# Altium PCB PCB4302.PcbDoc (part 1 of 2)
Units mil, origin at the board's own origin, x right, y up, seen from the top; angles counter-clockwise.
Board outline 1574.8 x 1476.38 mil, 4 copper layers (Top, Inner Layer 2, Inner Layer 3, Bottom), stack 35.4 mil thick; 37 components, 68 nets, 208 pads, 290 vias.
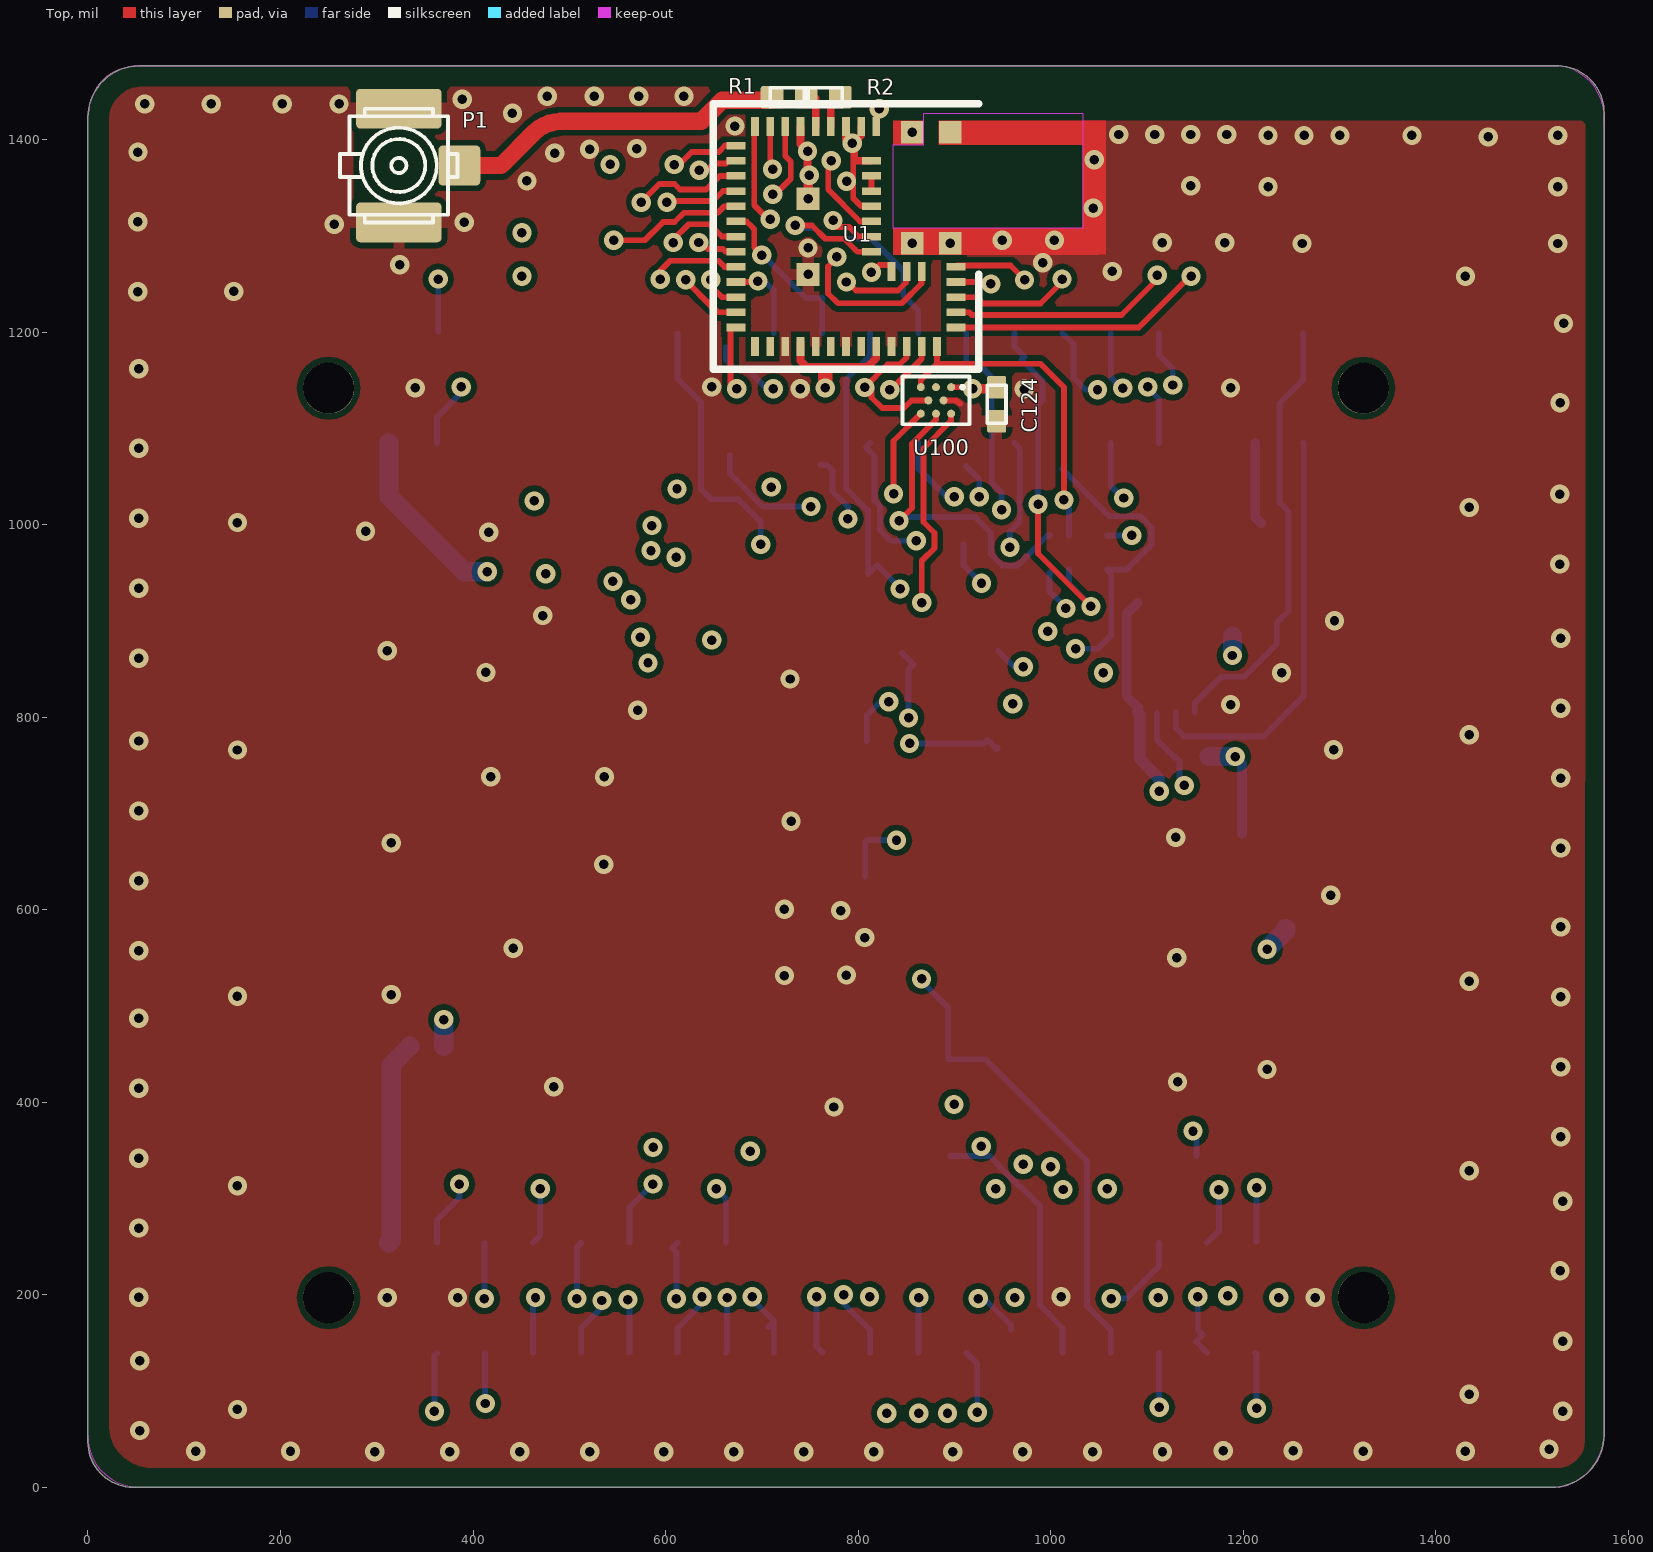
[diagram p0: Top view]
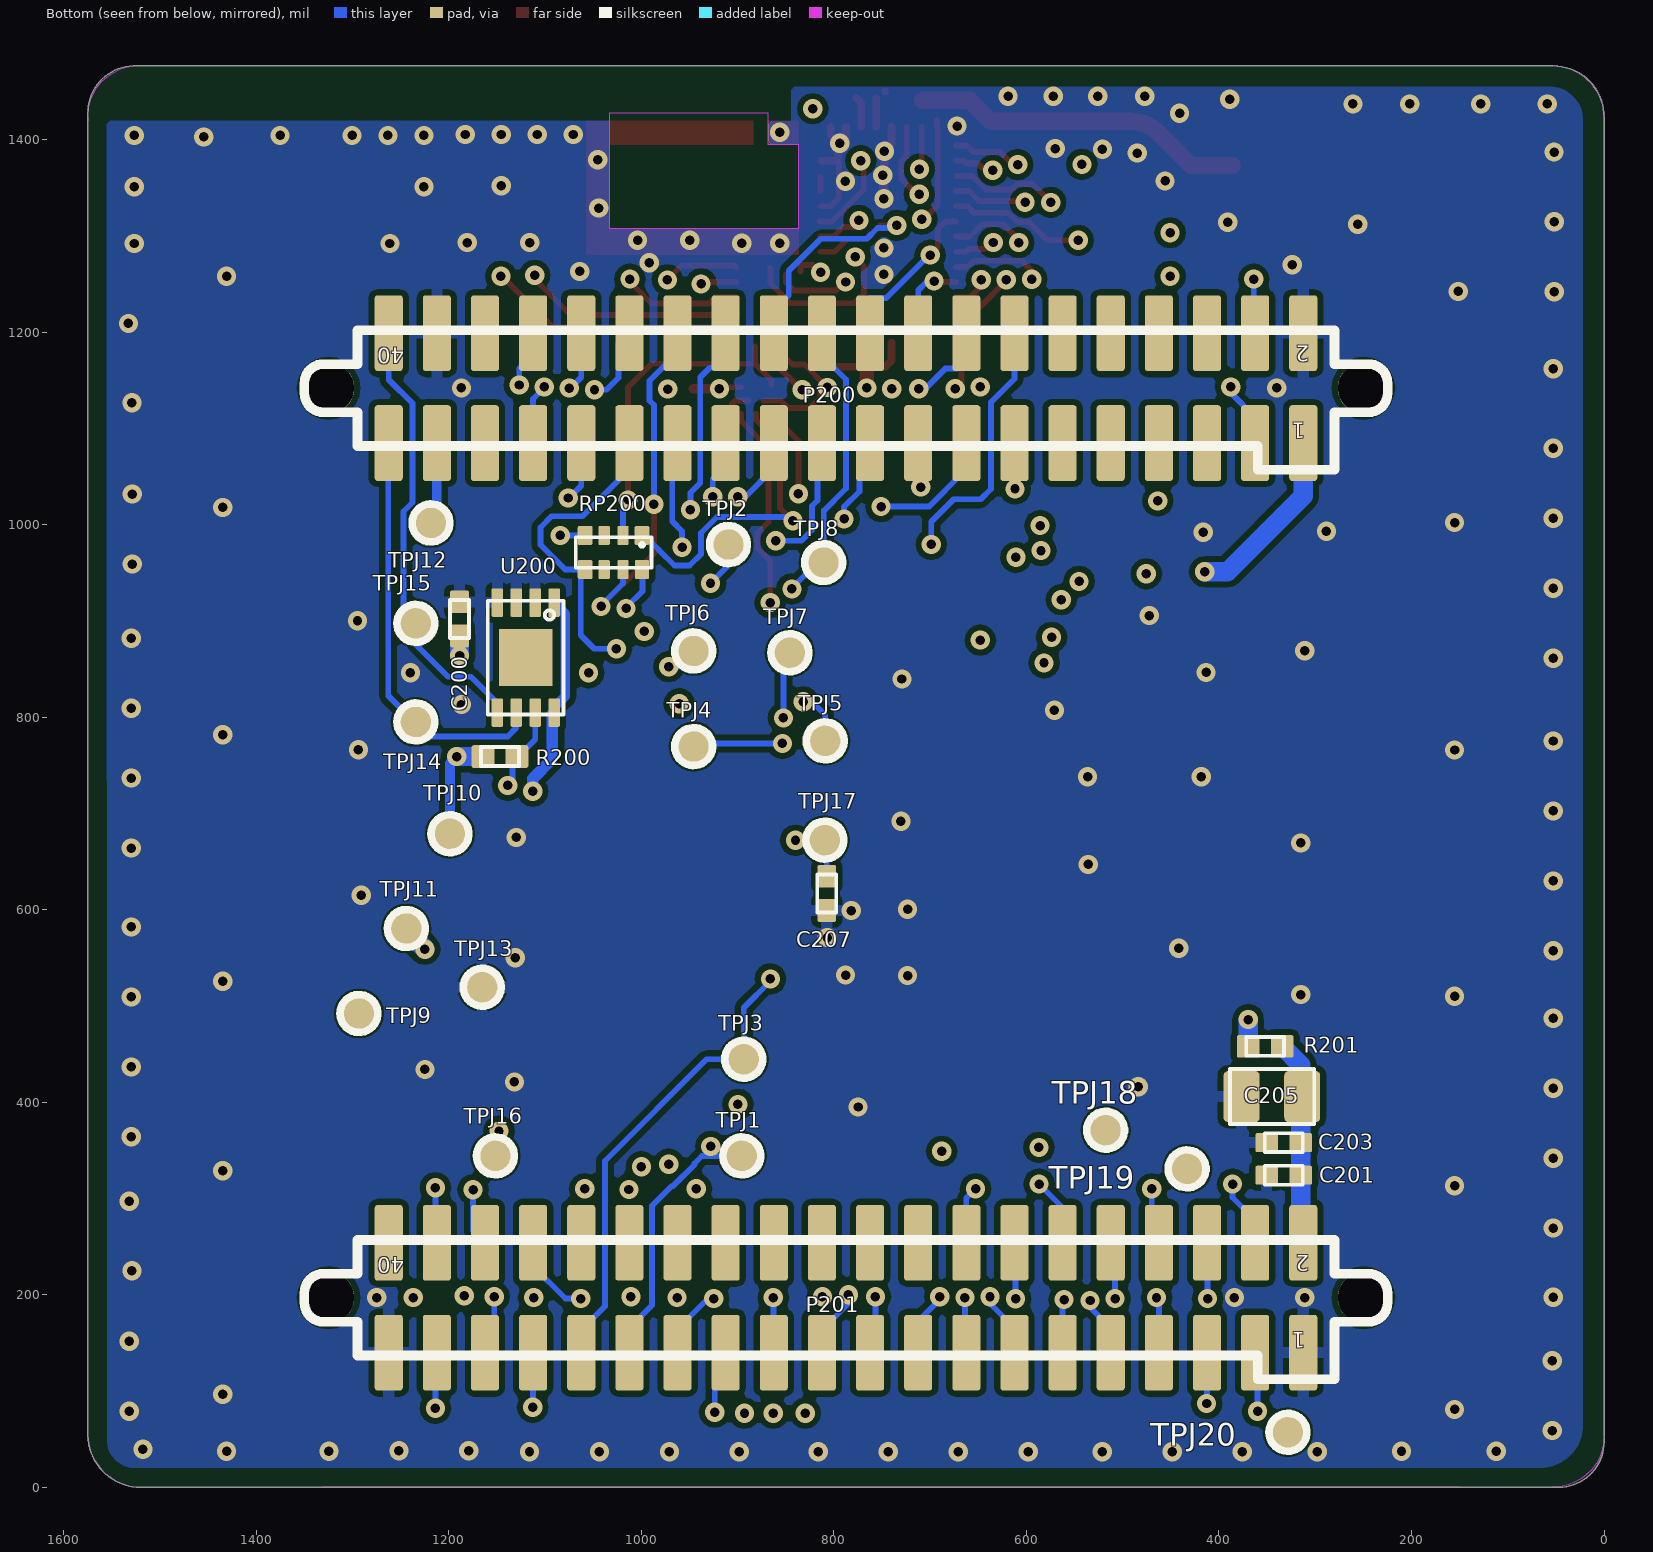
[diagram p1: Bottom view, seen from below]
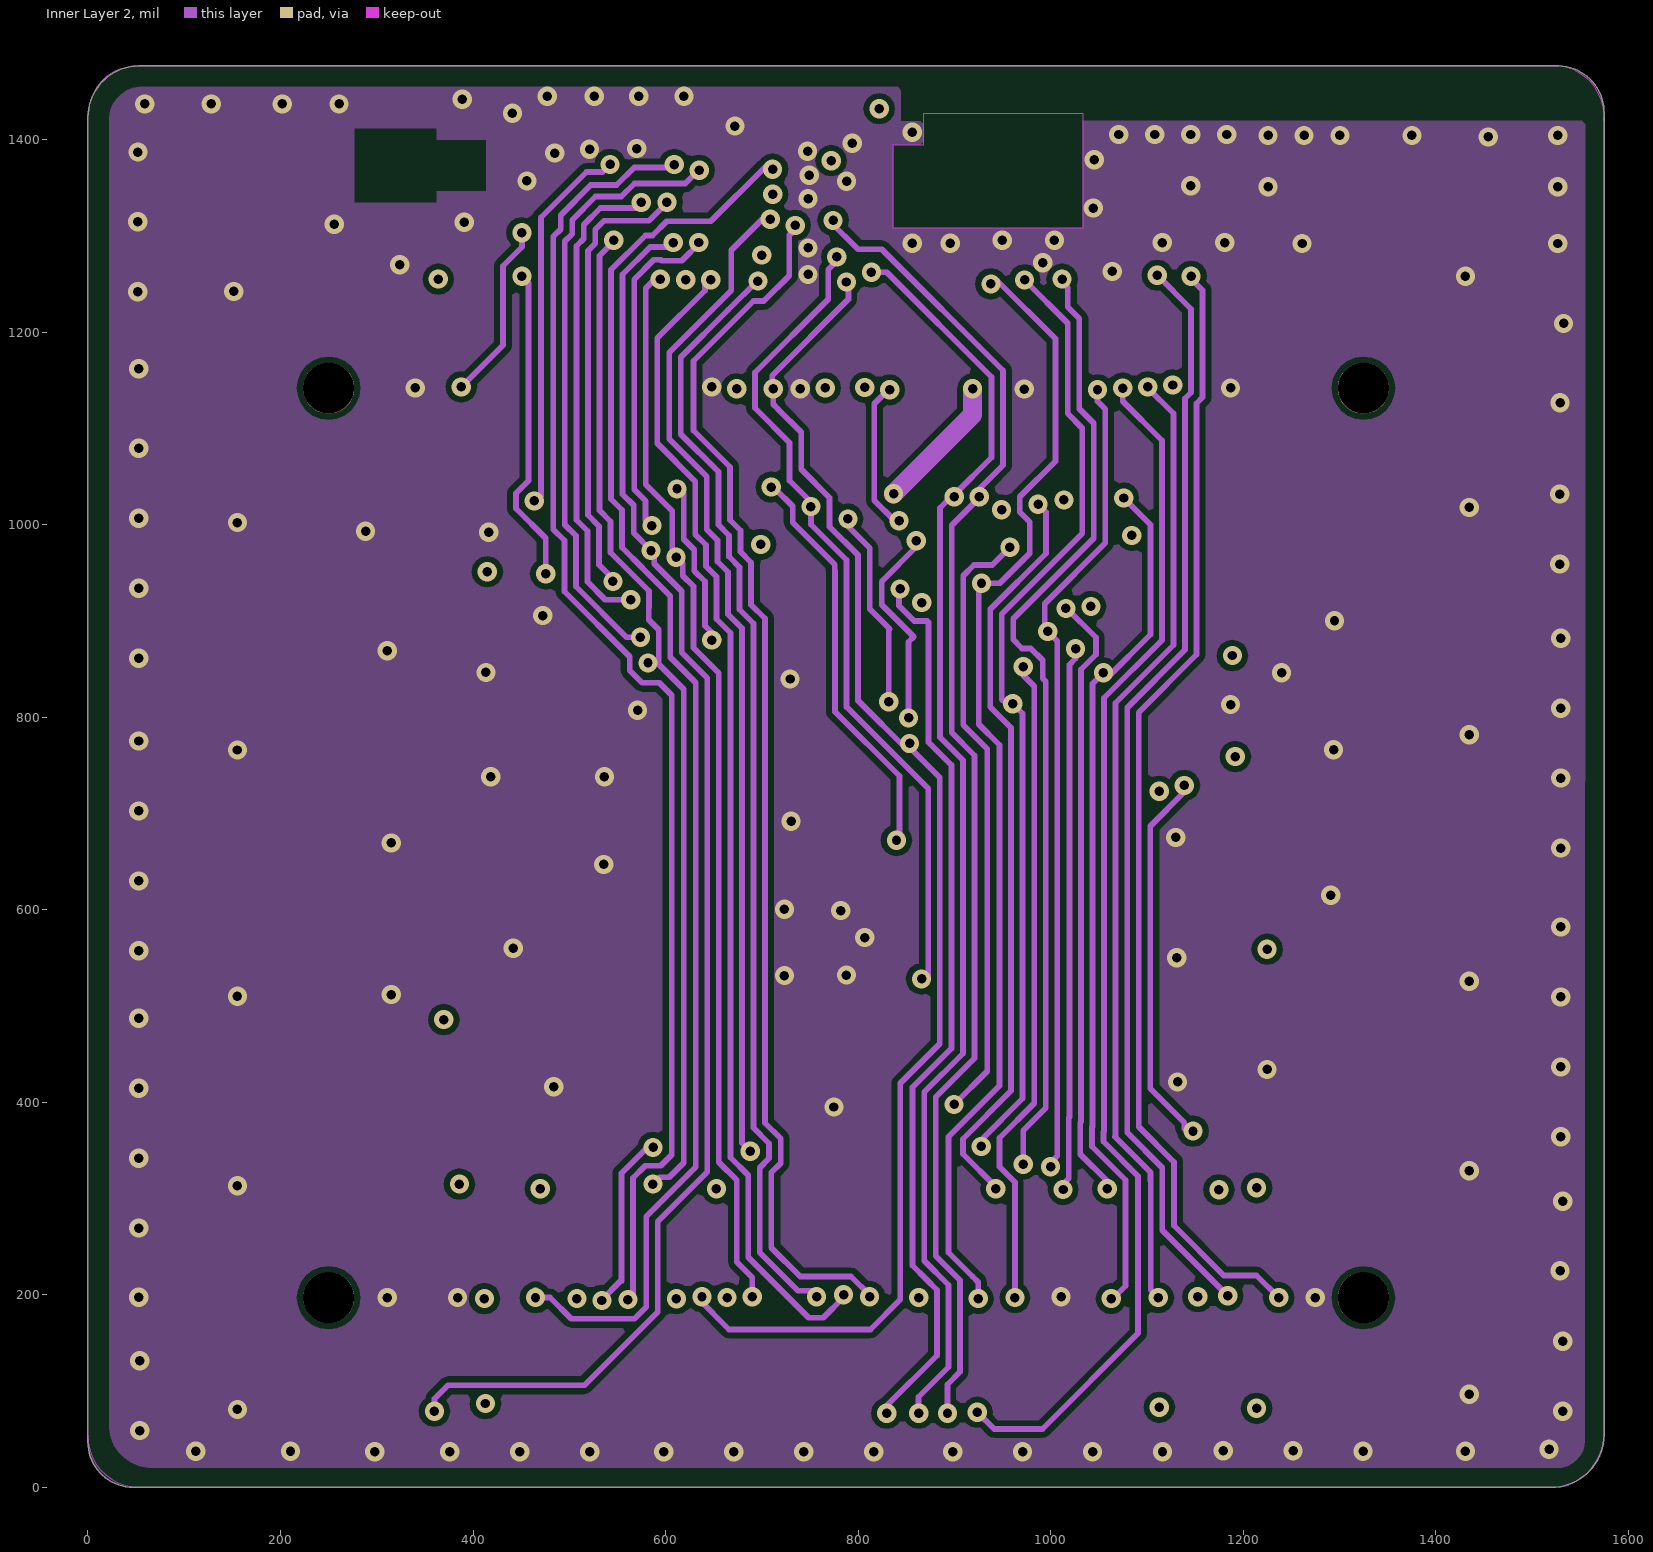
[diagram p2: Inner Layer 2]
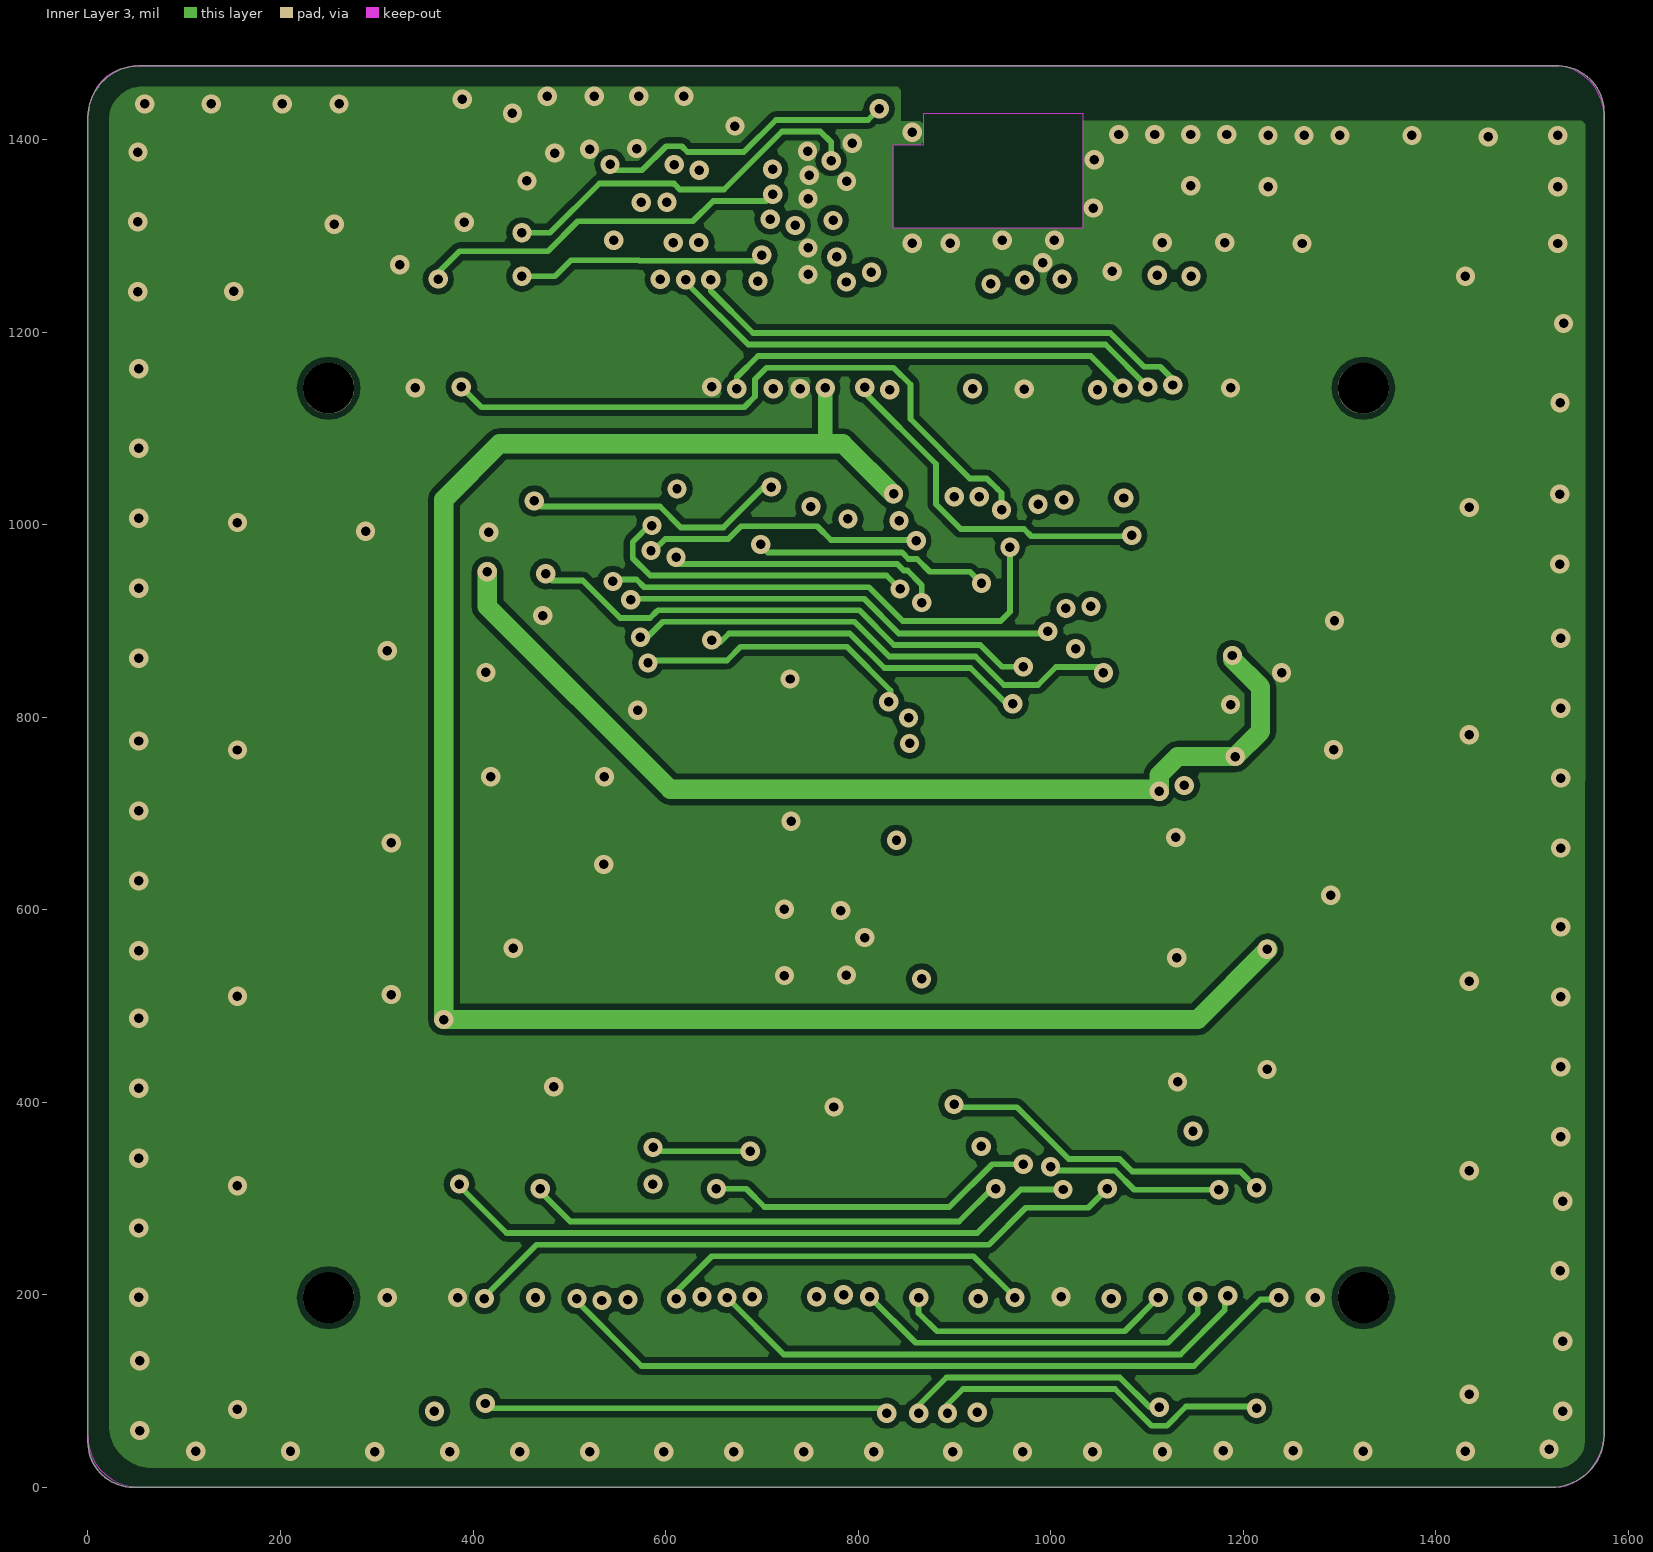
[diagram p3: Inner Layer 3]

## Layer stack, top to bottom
Solder Mask Top: solder mask 0.4, Solder Resist, Dk 3.5
Top: signal copper 1.35
Dielectric 1: dielectric 10, FR-4, Dk 4.3
Inner Layer 2: signal copper 1.35
Dielectric2: dielectric 10, FR-4, Dk 4.3
Inner Layer 3: signal copper 1.35
Dielectric3: dielectric 10, FR-4, Dk 4.3
Bottom: signal copper 1.35
Solder Mask Bottom: solder mask 0.4, Solder Resist, Dk 3.5

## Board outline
46.75,0 cw(c46.96,46.96) 0,47.18 0,1423.11 cw(c53,1423.38) 52.74,1476.38 1527.85,1476.38 cw(c1526.72,1428.3) 1574.8,1427.17 1574.8,54.22 cw(c1520.4,54.4) 1520.21,0

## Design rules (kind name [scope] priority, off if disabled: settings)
Clearance [All] p1: gap=6
Clearance 50Ohm [InNet('NetP1_1')] p2: gap=10
ComponentClearance "ComponentClearance -jumper overlap" [InComponent('R1') OR InComponent('R2') OR InComponent('U1') vs InComponent('R1') OR InComponent('R2') OR InComponent('U1')] p1: gap=0 collisioncheckmode=3 verticalgap=0 showdistances=FALSE
ComponentClearance "ComponentClearance - Default - DEFAULT" [All] p2: gap=6 collisioncheckmode=3 verticalgap=10 showdistances=FALSE
FanoutControl Fanout_Small [(CompPinCount < 5)] p3: bgadir=Out bgaviamode=Centered fanoutstyle=Auto fanoutdirection=OutThenIn viagrid=1 // Fanout_Small (Default Rule)
FanoutControl Fanout_SOIC [IsSOIC] p4: bgadir=Out bgaviamode=Centered fanoutstyle=Auto fanoutdirection=Alternating viagrid=1 // Fanout_SOIC (Default Rule)
HoleToHoleClearance HoleToHoleClearance-U1toPAD [Incomponent('U1') vs IsVia] p1: gap=0 allowstackedmicrovias=TRUE
HoleToHoleClearance HoleToHoleClearance-AT1toPAD [Incomponent('AT1') vs IsPAD] p2: gap=0 allowstackedmicrovias=TRUE
HoleToHoleClearance HoleToHoleClearance-U201toPAD [Incomponent('U201') vs IsVia] p3: gap=0 allowstackedmicrovias=TRUE
HoleToHoleClearance "HoleToHoleClearance - Default - DEFAULT" [All] p4: gap=6 allowstackedmicrovias=TRUE
MaxMinImpedance "Default Impedance" [All] p1: minimum=50.00 maximum=150.0
MinimumSolderMaskSliver [All] p1: minsoldermaskwidth=4
PlaneClearance [All] p1: clearance=6
PlaneConnect "Default PlaneConnect" [All] p1: planeconnectstyle=Relief reliefexpansion=20 reliefentries=4 reliefconductorwidth=16 reliefairgap=6
PolygonConnect "PolygonConnect _ GND Via" [IsVIa] p1: connectstyle=Direct reliefconductorwidth=10 reliefentries=4 polygonreliefangle="90 Angle" airgapwidth=10
PolygonConnect "PolygonConnect - Default SMT" [IsSMTPin] p2: connectstyle=Relief reliefconductorwidth=12 reliefentries=4 polygonreliefangle="90 Angle" airgapwidth=6
PolygonConnect "PolygonConnect - Default Pad" [All] p3: connectstyle=Relief reliefconductorwidth=16 reliefentries=4 polygonreliefangle="45 Angle" airgapwidth=6
RoutingLayers "RoutingLayers - Default - DEFAULT" [All] p1: top layer_v5=TRUE mid layer 1_v5=TRUE mid layer 2_v5=TRUE bottom layer_v5=TRUE
RoutingPriority "RoutingPriority - Default - DEFAULT" [All] p1: routingpriority=3
RoutingTopology "Default Routing Topology" [All] p1: topology=Shortest
RoutingVias "RoutingVias - Default - DEFAULT" [All] p1: holewidth=6 width=15 viastyle="Through Hole" minholewidth=6 minwidth=15 maxholewidth=10 maxwidth=20
SilkToSilkClearance [All] p1: silktosilkclearance=4
SilkToSolderMaskClearance [IsPad] p1: minsilkscreentomaskgap=4 clearancetoexposedcopper=TRUE
SolderMaskExpansion SolderMaskExpansion_via [IsVia] p1: expansion=-100
SolderMaskExpansion [All] p2: expansion=2
Width "Default Width" [All] p1: maxlimit=50 minlimit=6 preferedwidth=6 minimp=50.000000 maximp=50.000000 favimp=50.000000
18 further rules are at their usual default settings.

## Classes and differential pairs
component class "01_ Title Page": PCB1
component class "02_ RF, Antenna and Pow": P1 R1 R2 SH101
component class "03_ EFR32 I_O Port Conn": C124 C207 RP200 U1 U100
component class "04_ WSTK Connectors & B": C200 C201 C203 C205 P200 P201 R200 R201 TPJ1 TPJ2 TPJ3 TPJ4 TPJ5 TPJ6 TPJ7 TPJ8 TPJ9 TPJ10 TPJ11 TPJ12 TPJ13 TPJ14 TPJ15 TPJ16 TPJ17 TPJ18 TPJ19 TPJ20 U200
net class RADIO_PA[5..0]: RADIO_PA0 RADIO_PA1 RADIO_PA2 RADIO_PA3 RADIO_PA4 RADIO_PA5
net class RADIO_PB[15..11]: RADIO_PB11 RADIO_PB12 RADIO_PB13 RADIO_PB14 RADIO_PB15
net class RADIO_PC[11..6]: RADIO_PC6 RADIO_PC7 RADIO_PC8 RADIO_PC9 RADIO_PC10 RADIO_PC11
net class RADIO_PD[15..9]: RADIO_PD9 RADIO_PD10 RADIO_PD11 RADIO_PD12 RADIO_PD13 RADIO_PD14 RADIO_PD15
net class RADIO_PF[7..0]: RADIO_PF0 RADIO_PF1 RADIO_PF2 RADIO_PF3 RADIO_PF4 RADIO_PF5 RADIO_PF6 RADIO_PF7
net class WSTK_F[21..0]: WSTK_F4 WSTK_F15 WSTK_F16
net class WSTK_P[45..0]: WSTK_P3 WSTK_P15 WSTK_P17 WSTK_P19 WSTK_P21 WSTK_P23 WSTK_P25 WSTK_P27 WSTK_P29 WSTK_P38 WSTK_P39 WSTK_P40 WSTK_P41 WSTK_P42 WSTK_P43 WSTK_P44 WSTK_P45

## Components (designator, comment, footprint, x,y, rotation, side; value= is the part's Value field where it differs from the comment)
C124 "0.1uF" C0402_L 943.9,1125 r270 top
C200 "100N" C0402_L 1188.85,902 r90 bottom
C201 "100N" C0402_L 332.67,324.14 r0 bottom
C203 "100N" C0402_L 332.67,357.99 r0 bottom
C205 "10U" C0805_L 344.97,405.82 r0 bottom
C207 "100N" C0402_L 807.4,616.85 r270 bottom
P1 "U.FL" "COAX_HIROSE_U.FL_CL331-0471 - duplicate" 322.85,1373 r270 top
P200 "SOCKET_2X20_1.27MM_SMD" SAM_SFC-120-T2-D-A-2X20_SNUM 787.4,1141.73 r0 bottom locked
P201 "SOCKET_2X20_1.27MM_SMD" SAM_SFC-120-T2-D-A-2X20_SNUM 787.4,196.85 r0 bottom locked
R1 "0R" R0402_L 728.35,1443.9 r180 top
R2 "0R" R0402_L 763.78,1443.9 r180 top
R200 "10K" R0402_L 1146.85,759 r0 bottom
R201 "0R" R0402_L 351.96,457.99 r0 bottom
RP200 "100R" RES_MNR04-8 1028.85,971 r0 bottom
TPJ1 "PCB_PAD" TP_1.0_SMD 895.67,344.21 r180 bottom locked
TPJ2 "PCB_PAD" TP_1.0_SMD 909.45,979.25 r180 bottom locked
TPJ3 "PCB_PAD" TP_1.0_SMD 893.7,444.61 r180 bottom locked
TPJ4 "PCB_PAD" TP_1.0_SMD 945.67,769.41 r180 bottom locked
TPJ5 "PCB_PAD" TP_1.0_SMD 809.05,775.32 r180 bottom locked
TPJ6 "PCB_PAD" TP_1.0_SMD 945.67,868.72 r180 bottom locked
TPJ7 "PCB_PAD" TP_1.0_SMD 845.67,866.93 r180 bottom locked
TPJ8 "PCB_PAD" TP_1.0_SMD 810.63,960.63 r180 bottom locked
TPJ9 "PCB_PAD" TP_1.0_SMD 1293.31,492.13 r180 bottom locked
TPJ10 "PCB_PAD" TP_1.0_SMD 1198.82,678.86 r180 bottom locked
TPJ11 "PCB_PAD" TP_1.0_SMD 1244.09,580.43 r180 bottom locked
TPJ12 "PCB_PAD" TP_1.0_SMD 1218.5,1001.69 r180 bottom locked
TPJ13 "PCB_PAD" TP_1.0_SMD 1165.35,519.41 r180 bottom locked
TPJ14 "PCB_PAD" TP_1.0_SMD 1234.25,795 r180 bottom locked
TPJ15 "PCB_PAD" TP_1.0_SMD 1234.25,897.36 r180 bottom locked
TPJ16 "PCB_PAD" TP_1.0_SMD 1151.57,344.21 r180 bottom locked
TPJ17 "PCB_PAD" TP_1.0_SMD 809.35,672.23 r180 bottom locked
TPJ18 "PCB_PAD" TP_1.0_SMD 517.72,370.87 r90 bottom
TPJ19 "PCB_PAD" TP_1.0_SMD 433.07,330.71 r90 bottom
TPJ20 "PCB_PAD" TP_1.0_SMD 328.35,57.09 r90 bottom
U1 "BGM121" EFR_SIP 787.4,1299.21 r270 top
U100 "MX25R8035F" BGA8_M040_1.24x1.75_WLCSP 880.85,1129 r270 top
U200 "24AA024" TDFN8_M050_2.0x3.0_EP 1120.08,861.81 r0 bottom

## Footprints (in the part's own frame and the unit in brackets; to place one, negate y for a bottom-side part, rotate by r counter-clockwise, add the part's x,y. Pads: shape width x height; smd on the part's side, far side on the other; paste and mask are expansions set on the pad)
BGA8_M040_1.24x1.75_WLCSP [mm] "BGA, 8 pin. U100"
  round 0.21 smd mask+0.051: A1(-0.35,0.4) A3(0.35,0.4) B2(0,0.2) C1(-0.35,0) C3(0.35,0) D2(0,-0.2) E1(-0.35,-0.4) E3(0.35,-0.4)
  silkscreen extent -0.63,-0.89 0.63,0.88, body extent -0.63,-0.89 0.63,0.88, height 0.52
C0402_L [mm] "Chip Capacitor, 2-Leads, Body 1.0x0.5mm, IPC High Density"
  rrect20% 0.6x0.5 smd mask+0.051: 1(-0.45,0) 2(0.45,0)
  silkscreen extent -0.5,-0.25 0.5,0.25, body extent -0.5,-0.25 0.5,0.25, height 0.6
C0805_L [mm]
  rrect25% 0.95x1.35 smd: 1(-0.8,0) 2(0.8,0)
  silkscreen extent -1.12,-0.72 1.1,0.72, body extent -1.1,-0.72 1.1,0.72, height 1.45
"COAX_HIROSE_U.FL_CL331-0471 - duplicate" [mm]
  rrect20% 1.05x1.1 smd mask+0.051: 1(0,1.6)
  rrect20% 1.05x2.25 smd mask+0.051: 2(-1.5,0) 3(1.5,0)
  Top pour cut-out: -0.85,0.9 0.85,0.9 0.85,0.9 0.85,-1.2 -0.85,-1.2 -0.85,-1.2
  silkscreen extent -1.5,-1.55 1.5,1.55, body extent -1.3,-1.55 1.3,1.3, height 0.9
EFR_SIP [mm]
  rect 0.5x0.2 smd mask+0.015: 1(-2.9,0.8) 2(-2.9,0.4) 3(-2.9,0) 4(-2.9,-0.4) 5(-2.9,-0.8) 6(-2.9,-1.2) 7(-2.9,-1.6) 8(-2.9,-2) 9(-2.9,-2.4) 23(2.9,-2.4) 24(2.9,-2) 25(2.9,-1.6) 26(2.9,-1.2) 27(2.9,-0.8) 28(2.9,-0.4) 29(2.9,0) 30(2.9,0.4) 31(2.9,0.8) 32(2.9,1.2) 33(2.9,1.6) 34(2.9,2) 35(2.9,2.4) 41(0.925,2) 42(0.925,1.6) 43(0.925,1.2)
  rect 0.2x0.5 smd mask+0.015: 10(-2.4,-2.9) 11(-2,-2.9) 12(-1.6,-2.9) 13(-1.2,-2.9) 14(-0.8,-2.9) 15(-0.4,-2.9) 16(0,-2.9) 17(0.4,-2.9) 18(0.8,-2.9) 19(1.2,-2.9) 20(1.6,-2.9) 21(2,-2.9) 22(2.4,-2.9) 36(2.4,2.9) 37(2,2.9) 38(1.6,2.9) 39(1.2,2.9) 40(0.8,2.9) 44(0.4,0.675) 45(0,0.675) 46(-0.4,0.675) 47(-0.8,0.675) 48(-1.2,0.675) 49(-1.6,0.675) 50(-2,0.675)
  rect 0.6x0.6 smd mask+0.015: 51(-1,-1) 52(1,-1) 53(-2.75,2.75) 54(-2.75,1.75) 55(0.175,1.75) 56(0.175,2.75)
  Top region: -3.05,2.05 -3.05,1.25 -2.425,1.25 -2.425,2.05
  Top region: -0.225,3.05 -0.225,1.25 0.475,1.25 0.475,3.05
  Top pour cut-out: -0.225,1.25 -2.425,1.25 -2.425,2.05 -3.25,2.05 -3.25,2.45 -2.425,2.45 -2.425,6.25 -0.225,6.25
  Top region: -3.05,2.45 -2.425,2.45 -2.425,6.65 -3.05,6.65
  Top region: -3.05,6.25 0.463,6.25 0.463,6.85 -3.05,6.85
  Top region: -0.225,2.45 0.475,2.45 0.475,6.65 -0.225,6.65
  Keep-Out Layer pour cut-out: -3.25,6.25 -0.225,6.25 -0.225,1.25 -2.425,1.25 -2.425,2.05 -3.25,2.05 -3.25,2.45
  silkscreen extent -3.5,-3.5 3.5,3.5
R0402_L [mm] "Chip Resistor, 2-Leads, Body 1.0x0.5mm, IPC High Density"
  rrect20% 0.6x0.6 smd mask+0.051: 1(-0.45,0) 2(0.45,0)
  silkscreen extent -0.5,-0.25 0.5,0.25, body extent -0.5,-0.25 0.5,0.25, height 0.6
RES_MNR04-8 [mm] "Chip resistor network 8pin"
  rrect20% 0.39x0.5 smd mask+0.051: 1(-0.75,-0.45) 4(0.75,-0.45) 5(0.75,0.45)
  rrect20% 0.3x0.5 smd mask+0.051: 2(-0.25,-0.45) 3(0.25,-0.45) 6(0.25,0.45) 7(-0.25,0.45)
  rrect20% 0.38x0.5 smd mask+0.051: 8(-0.75,0.45)
  silkscreen extent -1,-0.4 1,0.4, body extent -1,-0.4 1,0.4, height 0.5
SAM_SFC-120-T2-D-A-2X20_SNUM [mm]
  rrect20% 0.74x2 smd mask+0.05: 1(-12.065,1.45) 2(-12.065,-1.45) 3(-10.795,1.45) 4(-10.795,-1.45) 5(-9.525,1.45) 6(-9.525,-1.45) 7(-8.255,1.45) 8(-8.255,-1.45) 9(-6.985,1.45) 10(-6.985,-1.45) 11(-5.715,1.45) 12(-5.715,-1.45) 13(-4.445,1.45) 14(-4.445,-1.45) 15(-3.175,1.45) 16(-3.175,-1.45) 17(-1.905,1.45) 18(-1.905,-1.45) 19(-0.635,1.45) 20(-0.635,-1.45) 21(0.635,1.45) 22(0.635,-1.45) 23(1.905,1.45) 24(1.905,-1.45) 25(3.175,1.45) 26(3.175,-1.45) 27(4.445,1.45) 28(4.445,-1.45) 29(5.715,1.45) 30(5.715,-1.45) 31(6.985,1.45) 32(6.985,-1.45) 33(8.255,1.45) 34(8.255,-1.45) 35(9.525,1.45) 36(9.525,-1.45) 37(10.795,1.45) 38(10.795,-1.45) 39(12.065,1.45) 40(12.065,-1.45)
  round 1.35 hole 1.35 unplated paste-5.563 mask-5.563: M1(13.652,0) M2(-13.652,0)
  silkscreen extent -14.29,-1.53 14.29,2.15, body extent -14.65,-1.58 14.65,2.25, height 4.57
TDFN8_M050_2.0x3.0_EP [mm] "TDFN8_M050_2.0x3.0_EP"
  rrect20% 0.3x0.75 smd mask+0.051: 1(-0.75,-1.45) 2(-0.25,-1.45) 3(0.25,-1.45) 4(0.75,-1.45) 5(0.75,1.45) 6(0.25,1.45) 7(-0.25,1.45) 8(-0.75,1.45)
  rect 1.4x1.5 smd mask+0.051: 9(0,0)
  silkscreen extent -1,-1.5 1,1.5, body extent -1,-1.5 1,1.5, height 1
TP_1.0_SMD [mm]
  round 1 smd paste-0.501: 1(0,0)
  silkscreen extent -0.5,-0.5 0.5,0.5

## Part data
C124: library part CAP_NP, "CAP, 0.1uF, 10V, ±10%, X7R, 0402"
C200 C207: library part CAPACITOR
C201 C203: library part C0402
C205: library part C0805
P1: library part HIROSE_U.FL
R1 R2 R201: library part R0402
R200: library part RESISTOR
RP200: library part MNR04M0APJ101
TPJ1 TPJ2 TPJ3 TPJ4 TPJ5 TPJ6 TPJ7 TPJ8 TPJ9 TPJ10 TPJ11 TPJ12 TPJ13 TPJ14 TPJ15 TPJ16 TPJ17 TPJ18 TPJ19 TPJ20: "PCB Feature, SINGLE PAD, SMD"
U100: library part MX25R8035, "Flash, Serial, 8M"

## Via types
v1: diameter 20, hole 9.84, Top to Bottom, tented both sides, 290 vias

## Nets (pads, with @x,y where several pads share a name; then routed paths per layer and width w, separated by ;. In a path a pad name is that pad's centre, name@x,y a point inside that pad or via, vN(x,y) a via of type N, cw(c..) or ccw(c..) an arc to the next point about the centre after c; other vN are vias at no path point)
3V3: C200.1 P200.1 R200.2 TPJ10.1 U200.1 U200.8 | length 1575
  Inner Layer 3 w20: v1(414.85,951) 414.85,914.87 604.72,725 1110.85,725 v1(1112.85,723) 1112.85,739.77 1132.08,759 v1(1191.85,759) 1217.85,785 1217.85,831.23 1188.85,860.23 v1(1188.85,864)
  Bottom w10: U200.1@1090.55,918.9 1078.85,907.2 1078.85,822 U200.8@1090.85,810 ; v1(1191.85,759) 1198.82,752.04 TPJ10.1@1198.82,678.86
  Bottom w12: U200.8@1090.85,804.43 1092.33,802.94 1092.33,756.59 1112.85,736.07 v1(1112.85,723)
  Bottom w20: P200.1@312.4,1084.65 312.4,1029.68 391.08,951 v1(414.85,951) ; R200.2@1164.57,759 v1(1191.85,759) ; v1(1188.85,864) C200.1@1188.85,884.28
5V: P200.37 TPJ12.1 | length 85.5
  Bottom w10: P200.37@1212.4,1084.65 1212.4,1007.79 TPJ12.1@1218.5,1001.69
BOARD_ID_SCL: P200.39 TPJ14.1 U200.6 | length 433
  Bottom w6: U200.6@1129.92,804.72 1129.92,788.93 1138.85,780 1220.85,780 1262.93,822.08 1262.93,1084.65 P200.39@1262.4,1084.65
BOARD_ID_SDA: P200.40 TPJ15.1 U200.5 | length 462.6
  Bottom w6: U200.5@1149.61,804.72 1149.61,814.76 1176.85,842 1200.85,842 1234.85,876 1234.85,898 1247.19,910.33 1247.19,1013.58 1237.85,1022.91 1237.85,1126 1262.4,1150.55 P200.40@1262.4,1198.82
BOARD_ID_WP: R200.1 TPJ16.1 U200.7 | length 514.3
  Inner Layer 2 w6: v1(1138.85,729) 1138.85,722.13 1103.46,686.74 1103.46,414.25 1138.85,378.85 1138.85,373 1141.85,370 v1(1147.85,370)
  Bottom w6: U200.7@1110.24,804.72 1110.24,776.61 R200.1@1128.85,758 ; R200.1@1129.13,759 1133.85,754.28 1133.85,729 v1(1138.85,729) ; v1(1147.85,370) 1151.57,366.28 TPJ16.1@1151.57,344.21
GND: C124.2 C200.2 C201.2 C203.2 C205.2 C207.2 P1.2 P1.3 P200.2 P200.38 P201.1 P201.39 TPJ13.1 U1.2 U1.3 U1.6 U1.25 U1.27 U1.29 U1.32 U1.47 U1.50 U1.51 U1.52 U1.53 U1.54 U1.55 U1.56 U100.B2 U200.2 U200.3 U200.4 | length 251.9
  Top w6: U1.52@742.01,1259.84 v1(748.03,1259.84) ; v1@787.4,1399.45 v1@791.85,1395 ; 795.85,1377.95 795.85,1376.56 794.93,1375.63 ; 795.85,1382 794.93,1381.08 794.93,1375.63 ; U1.47@813.98,1330.71 803.22,1330.71 794.93,1339 794.93,1348.09 795,1348.16 795,1375.56 794.93,1375.63 ; U100.B2@888.72,1129 902.5,1129 905.89,1125.61
  Top w8: U1.6@740.16,1413.39 740.16,1395.2 v1(747.46,1387.9) 747.46,1356.55 748.03,1357.12 v1@748.03,1361.76 ; v1@787.4,1399.45 U1.3@787.4,1413.39 ; v1@792.85,1396 795.85,1393 795.85,1382 ; 795.85,1377.95 U1.50@812.87,1377.95 ; v1@795.85,1397 803.15,1404.3 U1.2@803.15,1413.39
  Top w10: U1.51@748.03,1335.63 v1(748.03,1338.58) v1@748.03,1357.12
  other v1: 111.94,37.5 210.36,37.5 297.85,37 375.85,37 448.52,37 521.18,37 598.18,37 670.85,37 743.52,37 816.18,37 898.18,37 970.85,37 1043.52,37 1116.18,37 1324.54,37.5 1430.83,37.5 1179.18,38 1251.85,38 1517.72,39.37 53.75,58.87 1531.83,79 155.24,80.8 1434.77,96.55 53.75,131.54 1531.83,151.67 52.75,197.32 310.85,197 383.85,197 1274.85,197 1010.85,198 1529.13,224.88 52.75,269.21 1531.83,297 155.24,313.09 1434.77,328.83 52.75,341.87 1529.83,364 774.85,395 52.75,414.54 483.85,416 1131.85,421 1224.85,434 1529.83,436.67 52.75,487.21 1529.83,509.33 155.24,509.94 314.96,511.81 1434.77,525.68 723.43,531.5 787.85,532 1130.85,550 52.75,557.21 441.85,560 806.85,571 1529.83,582 781.85,599 723.43,600.39 1290.85,615 52.75,629.87 535.85,647 1529.83,664 314.96,669.29 1129.85,675 730.31,691.93 52.75,702.54 1529.83,736.67 418.31,738.19 536.42,738.19 155.24,765.84 1293.85,766 52.75,775.21 1434.77,781.59 570.87,807.09 1529.83,809.33 1186.85,813 729.36,839.61 413.39,846.46 1239.85,846 52.75,861.21 310.85,869 1529.83,882 1294.85,900 472.44,905.51 52.75,933.87 1528.83,959 416.34,992.13 288.39,993.11 155.24,1002.06 52.75,1006.54 1434.77,1017.81 1528.83,1031.67 52.75,1079.21 1529.13,1126.45 739.85,1141 972.44,1140.75 339.85,1142 1186.85,1142 647.85,1143 52.75,1161.88 1532.83,1209 51.75,1241.87 151.31,1242.22 1430.83,1257.97 1063.85,1263 323.85,1270 991.85,1272 748.03,1287.4 856.3,1292.32 895.67,1292.32 1261.18,1292 1526.83,1292 1115.85,1293 1180.85,1293 949.8,1295.28 1003.94,1295.28 255.85,1312 51.75,1314.54 390.85,1314 1044.29,1328.74 1225.85,1351 1526.83,1351 1145.52,1352 456,1357 787.98,1356.77 749.11,1362.84 1045.28,1378.94 484.91,1385.89 51.85,1387 521,1390 569.94,1390.59 793.85,1396 1454.46,1402.65 1225.85,1404.2 1263.18,1404.2 1300.52,1404.2 1375.32,1404.2 1526.83,1404.2 1070.85,1405.2 1108.18,1405.2 1145.52,1405.2 1182.85,1405.2 856.3,1407.48 672,1414 440.94,1427.17 59.06,1437.01 127.95,1437.01 201.77,1437.01 260.83,1437.01 388.78,1441.93 477,1445 526,1445 572,1445 619,1445
NetP1_1: P1.1 R1.2 | length 348.1
  Top w18: P1.1@385.84,1373 429.11,1373 463.23,1407.12 cw(c491.22,1379.13) 491.22,1418.71 ; 491.22,1419 637,1419 658.93,1440.93 R1.2@707.66,1440.93
NetR1_1: R1.1 R2.2 U1.5 | length 30.2
  Top w8: R1.1@746.57,1450 R1.1@747.13,1450 ; U1.5@755.91,1413.39 R1.1@755.91,1443
NetR2_1: R2.1 U1.4 | length 31.4
  Top w8: U1.4@771.65,1413.39 771.65,1437.8 R2.1@776.57,1442.72
NetU1_48: U1.48 U1.49 | length 14.8
  Top w6: U1.48@813.98,1346.46 U1.49@813.98,1361.22
RADIO_PA0: P200.19 P201.12 TPJ5.1 U1.14 | length 1882.8
  Top w6: v1@547.24,1295.28 578.44,1295.28 597.44,1314.28 609.29,1314.28 619.03,1324.02 654.26,1324.02 660.95,1330.71 U1.14@673.23,1330.71
  Inner Layer 2 w6: v1@546.26,1294.29 531.35,1279.38 531.35,1014.83 542.85,1003.32 542.85,970.93 582.85,930.93 582.85,914.13 582.49,913.77 582.49,901.23 592.85,890.87 592.85,856.34 ; v1(586.85,315) 593.85,322 603.75,322 618.91,337.16 618.91,828.93 592.85,854.98 ; v1(789.37,1005.91) 789.37,998.29 812.01,975.65 812.01,912.29 832.85,891.45 831.72,890.32 v1(831.72,815.98)
  Inner Layer 3 w6: v1@580.71,855.31 584.29,858.89 663.74,858.89 677.85,873 788.42,873 833.66,827.76 833.66,816.81 832.84,815.98 v1(831.72,815.98)
  Bottom w6: P201.12@562.4,253.94 562.4,290.55 v1(586.85,315) ; P200.19@760.83,1062.01 767.72,1062.01 773.5,1056.22 773.5,1034.33 789.37,1018.46 v1(789.37,1005.91) ; TPJ5.1@809.05,775.32 809.05,802.2 826.85,820 830.87,815.98 v1(831.72,815.98)
  other v1: 581.71,856.34 546.26,1295.28
RADIO_PA1: P200.20 P201.14 TPJ6.1 U1.15 | length 2454.9
  Top w6: U1.15@673.23,1314.96 684,1314.96 689.63,1309.33 692.07,1306.88 692.07,1287.93 v1(700,1280)
  Inner Layer 2 w6: v1@457.68,1250.98 457.68,1045.57 444.58,1032.48 444.58,1016.74 475.39,985.93 v1(475.39,948.82) ; v1(962.85,197) 962.85,316.87 946.85,332.87 946.85,362.87 982.85,398.87 982.85,832 971.46,843.39 971.49,843.43 v1(971.49,852.4)
  Inner Layer 3 w6: v1(450.79,1257.87) 485.24,1257.87 501.85,1274.48 572.13,1274.48 572.62,1274 694.25,1274 v1@700.04,1279.79 ; v1@482.21,942 513.85,942 552.85,903 583.85,903 590.85,910 591.01,910 592.01,911 801.33,911 837.33,875 926.79,875 949.39,852.4 v1(971.49,852.4) ; v1(611.24,195.88) 609.97,195.88 606.85,199 647.85,240 919.85,240 v1(962.85,197)
  Bottom w6: v1(611.24,195.88) 611.24,244 606.85,248.39 P201.14@612.4,253.94 ; v1(700,1280) 701,1280 745.56,1235.45 762.4,1235.45 P200.20@762.4,1198.82 ; TPJ6.1@945.67,868.72 961.98,852.4 v1(971.49,852.4)
RADIO_PA2: P200.21 P201.3 TPJ7.1 U1.16 | length 2345.3
  Top w6: v1(608,1293) 608,1296.02 624,1312.02 645.7,1312.02 658.51,1299.21 U1.16@673.23,1299.21
  Inner Layer 2 w6: v1(359.85,79) 359.85,92 373.85,106 515.69,106 591.85,182.16 591.85,276.16 643.28,327.59 643.28,840.73 616.85,867.16 616.85,930.87 588.29,959.43 v1@588.29,968.56 ; v1@584.85,973.13 566.85,991.13 566.85,1020.06 555.35,1031.56 555.35,1259.66 584.07,1288.39 608.27,1288.39 608.98,1289.1 608,1290.09 v1(608,1293) ; v1(852.36,799.21) 852.36,877.93 857.85,883.42 824.54,916.73 824.54,940.99 861.22,977.67 v1@861.22,982.28
  Inner Layer 3 w6: v1(584.85,973) 587.72,973 599.72,985 664.98,985 678.36,998.38 757.53,998.38 771.91,984 v1@859.98,984
  Bottom w6: v1(359.85,79) 359.85,137.21 P201.3@362.4,139.76 ; P200.21@812.4,1084.65 807.85,1080.09 816.93,1071.02 816.93,1025.05 822.63,1019.35 822.63,994.3 833.66,983.27 v1@860.27,983.27 ; TPJ7.1@845.67,866.93 857.85,854.75 852.36,849.26 v1(852.36,799.21)
  other v1: 860.27,983.32
RADIO_PA3: P200.22 P201.5 TPJ8.1 U1.17 | length 2443.6
  Top w6: v1@640.75,1289.37 643.7,1286.42 659.52,1286.42 659.66,1286.28 ; 659.69,1286.28 662.5,1283.46 U1.17@673.23,1283.46
  Inner Layer 2 w6: v1@579.27,1004.58 579.27,1024.61 567.35,1036.53 567.35,1254.69 587.66,1275 595.06,1275 596.06,1274 616.85,1274 635.83,1292.97 v1@635.83,1293.31 ; v1(829.85,77) 829.85,85 881.85,137 881.85,204.87 870.72,216 870.72,216.13 856.61,230.24 856.61,415.44 896.85,455.68 896.85,750.31 873.15,774.01 873.15,898.5 871.69,899.96 858.28,899.96 842.52,915.72 v1@842.52,933.07
  Inner Layer 3 w6: v1(412.85,87) 417.85,82 830.85,82 829.85,81 v1(829.85,77) ; v1(585.85,999) 585.85,1000 584.85,1001 565.85,982 565.85,965.13 583.98,947 829.57,947 v1(843.54,933.12)
  Bottom w6: P201.5@412.4,139.76 412.4,87.45 v1(412.85,87) ; 810.04,1014.76 787.4,1037.4 787.4,1150.59 812.4,1175.59 P200.22@812.4,1198.82 ; 810.14,1014.87 810.63,1014.38 TPJ8.1@810.63,960.63 810.63,948.78 819.7,957.85 843.54,934.02 v1(843.54,933.12)
  other v1: 634.49,1293.02
RADIO_PA4: P201.17 U1.18 U100.A3 | length 1788.2
  Top w6: v1(594.51,1254.98) 594.51,1263.66 604.85,1274 655,1274 661.28,1267.72 U1.18@673.23,1267.72 ; v1(866.15,918.96) 866.15,962.33 879.27,975.45 879.27,991.19 867.85,1002.6 867.85,1079 896.6,1107.75 U100.A3@896.6,1115.22
  Inner Layer 2 w6: v1(594.51,1254.98) 594.51,1260.57 579.35,1245.45 579.35,1041.5 606.85,1014 606.85,971 v1@609.85,968 ; v1@617.85,960 617.85,946.84 628.85,935.84 628.85,872.13 655.28,845.7 655.28,337.66 673.85,319.09 673.85,234 690,217.85 v1(690,198)
  Inner Layer 3 w6: v1@610.85,959 840.74,959 847.43,952.32 851.21,952.32 866.15,937.37 v1(866.15,918.96)
  Bottom w6: v1(690,198) 690,195.06 712.85,172.21 706.74,166.11 712.4,171.76 P201.17@712.4,139.76
  other v1: 610.85,966
RADIO_PA5: P200.18 P201.19 U1.19 | length 1307.4
  Top w6: U1.19@673.23,1251.97 694.88,1251.97 v1@695.87,1252.95
  Inner Layer 2 w6: v1(695.89,1253.01) 695.89,1253.88 695.85,1253.92 664.96,1223.03 615.85,1173.92 615.85,1093.81 654.85,1054.81 654.85,999.78 665.85,988.78 665.85,966.72 676.85,955.72 676.85,911.81 691.28,897.38 691.28,373.44 707.52,357.2 707.52,341.65 697.85,331.98 697.85,243.94 737.64,204.15 751.7,204.15 757.85,198 v1(756.85,198)
  Bottom w6: v1@703.39,1252.46 712.4,1243.45 P200.18@712.4,1198.82 ; v1(756.85,198) 756.85,146.21 762.85,140.21 P201.19@762.4,139.76
RADIO_PB11: P200.34 P201.21 U1.20 | length 1922.9
  Top w6: v1@645.67,1253.94 645.67,1249.02 658.46,1236.22 U1.20@673.23,1236.22 ; v1@647.85,1253.94 v1@647.85,1256
  Inner Layer 2 w6: v1(646.85,1254.35) 646.85,1254.55 646.13,1255.28 640.85,1250 640.85,1243.21 591.35,1193.71 591.35,1084.37 630.85,1044.87 630.85,989.84 641.85,978.84 641.85,956.78 652.85,945.78 652.85,901.87 667.28,887.44 667.28,353.15 667.32,353.11 667.32,342.59 685.85,324.06 685.85,238.97 748.82,176 763.85,176 784.85,197 v1(784.85,200)
  Inner Layer 3 w6: v1(646.85,1254.35) 646.85,1243 690.85,1199 1061.82,1199 1096.82,1164 1113.85,1164 1126.85,1151 v1(1126.85,1145)
  Bottom w6: v1(784.85,200) 784.85,191 812.4,163.45 P201.21@812.4,139.76 ; P200.34@1112.4,1198.82 1112.4,1176.45 1126.85,1162 v1(1126.85,1145)
RADIO_PB12: P200.33 P201.23 U1.21 | length 2004.1
  Top w6: v1@620.85,1254 620.85,1253.48 648.02,1226.3 648.55,1226.3 ; 648.62,1226.38 654.53,1220.47 U1.21@673.23,1220.47
  Inner Layer 2 w6: 1066.85,364.03 1103.85,327.03 1103.85,318 ; 1066.85,364.08 1067.46,364.68 1067.46,814.77 1127.57,874.88 1127.57,1115.28 1100.85,1142 v1(1100.85,1143) ; 1103.87,318 1103.99,204.83 v1(1111.85,197)
  Inner Layer 3 w6: v1@622.85,1253 622.85,1250 685.85,1187 1056.85,1187 v1(1100.85,1143) 1100.35,1143.5 v1@1102.35,1145.5 ; v1(862.85,197) 862.85,181 881.85,162 1076.85,162 v1(1111.85,197)
  Bottom w6: P201.23@862.4,139.76 862.85,140.21 v1(862.85,197) ; v1(1100.85,1143) 1100.85,1142 1112.4,1130.45 P200.33@1112.4,1084.65
  other v1: 620.85,1254.35
RADIO_PB13: P200.32 P201.25 U1.22 | length 1877.5
  Top w6: v1@667.32,1144.69 U1.22@667.32,1202.76
  Inner Layer 2 w6: v1(923.85,78) 941.3,60.55 991.4,60.55 1090.85,160 1090.85,200.99 1090.8,201.04 1090.75,201.09 1090.75,208.57 1090.85,208.67 1090.85,323.06 1054.85,359.06 1054.85,369.05 1055.46,369.65 1055.46,819.74 1115.57,879.85 1115.57,1087.28 1074.85,1128 v1(1074.85,1141.79)
  Inner Layer 3 w6: v1(673.85,1141) 673.85,1153 695.85,1175 1041.63,1175 v1(1074.85,1141.79)
  Bottom w6: P201.25@912.4,139.76 923.85,128.32 v1(923.85,78) ; P200.32@1062.4,1198.82 1062.4,1153.15 1073.76,1141.79 v1(1074.85,1141.79)
RADIO_PB14: U1.23
RADIO_PB15: U1.24
RADIO_PC6: RP200.4 U1.33 U100.D2 | length 540.3
  Top w6: v1(806.85,1142.43) 830.61,1166.2 843.08,1166.2 850.39,1173.51 U1.33@850.39,1185.04 ; v1@813.85,1142.43 813.85,1132.13 824.98,1121 847.31,1121 855.31,1129 U100.D2@872.98,1129
  Inner Layer 3 w6: v1(806.85,1142.43) 806.85,1137 880.85,1063 880.85,1021.13 906.55,995.43 972.39,995.43 979.81,988 1083.42,988 v1(1084.13,988.72)
  Bottom w6: RP200.4@1058.38,988.72 v1(1084.13,988.72)
RADIO_PC7: RP200.1 U1.34 U100.C3 | length 547.8
  Top w6: v1@832.85,1139 866.14,1172.29 U1.34@866.14,1185.04 U1.34@865.35,1184.25 ; v1(842.52,1003.94) 855.85,1017.27 855.85,1084 880.85,1109 U100.C3@880.85,1115.22
  Inner Layer 2 w6: v1@829.85,1140 829.85,1138.56 816.85,1125.56 816.85,1025.13 837.06,1004.92 v1@842.52,1004.92
  Bottom w6: v1(842.52,1003.94) 846.52,1007.94 921.33,1007.94 938.13,991.14 938.13,969.14 949.84,957.43 965.58,957.43 981.6,973.44 981.6,973.72 996.59,988.72 RP200.1@999.32,988.72
  other v1: 832.85,1140
RADIO_PC8: RP200.2 U1.35 U100.E1 | length 346.8
  Top w6: U100.E1@865.1,1145.35 865.1,1150.25 881.89,1167.04 ; U1.35@881.89,1185.04 881.89,1167.04 ; v1(1013.82,1025.64) 1013.82,1142.68 989.46,1167.04 881.89,1167.04
  Bottom w6: v1(1013.82,1025.64) 1017.21,1025.64 1019.01,1023.84 RP200.2@1019.01,988.72
RADIO_PC9: P201.10 U1.36 | length 2290
  Top w6: U1.36@901.57,1204.72 1091.57,1204.72 1144.85,1258 v1(1145.85,1258)
  Inner Layer 2 w6: 1127.85,338 1091.46,374.39 1091.46,804.82 1151.57,864.94 1151.57,1125.88 1157.85,1132.16 1157.85,1243.33 1145.85,1255.33 v1(1145.85,1258) ; 1127.99,338 1127.99,271.83 1179.82,220 1213.85,220 v1(1236.85,197)
  Inner Layer 3 w6: v1(507.85,196) 507.85,193.13 574.98,126 1148.85,126 1217.85,195 1236.85,195 v1(1236.85,197)
  Bottom w6: v1(507.85,196) 507.85,249.39 P201.10@512.4,253.94
RADIO_PC10: P201.15 U1.37 | length 2010.6
  Top w6: U1.37@900.59,1220.47 U1.37@901.57,1220.47 915.35,1220.47 918.11,1217.72 1073.57,1217.72 1110.85,1255 v1(1110.85,1259)
  Inner Layer 2 w6: v1(1110.85,1259) 1145.85,1224 1145.85,1137.13 1139.57,1130.85 1139.57,869.91 1079.46,809.8 1079.46,368.39 1115.85,332 ; 1115.99,332 1115.99,266.86 v1(1183.85,199)
  Inner Layer 3 w6: v1(663.85,197) 722.85,138 1134.85,138 1180.85,184 1180.85,196 v1(1183.85,199)
  Bottom w6: P201.15@662.4,139.76 663.85,141.21 v1(663.85,197)
RADIO_PC11: P201.16 U1.38 | length 1527.3
  Top w6: U1.38@901.57,1236.22 923.23,1236.22 929.13,1230.31 ; 929.01,1230.19 929.49,1229.72 989.57,1229.72 1011.85,1252 v1(1011.85,1255)
  Inner Layer 2 w6: v1(971.49,335.65) 971.49,370.54 994.85,393.9 994.85,836.97 991.67,840.15 991.67,859.1 979.36,871.4 970.32,871.4 961.2,880.52 961.2,902.13 1044.82,985.75 1044.82,1105.16 1029.72,1120.26 1029.72,1132.09 1029.67,1132.15 1029.67,1214.16 1017.85,1225.97 1017.85,1246 v1@1010.85,1253 ; v1@1011.85,1253 v1(1011.85,1255)
  Inner Layer 3 w6: v1(652.85,310) 683.85,310 702.85,291 894.72,291 939.37,335.65 v1(971.49,335.65)
  Bottom w6: v1(652.85,310) 662.4,300.45 662.4,279.55 P201.16@662.4,253.94
RADIO_PD9: P200.4 U1.7 | length 528.4
  Top w6: v1(711.32,1343.2) 711.32,1340.45 730.07,1359.2 730.07,1377.07 724.28,1382.86 U1.7@724.28,1413.12
  Inner Layer 3 w6: v1(363.85,1255) 363.85,1262 385.85,1284 477.85,1284 508.85,1315 628.27,1315 649.46,1336.19 704.31,1336.19 v1(711.32,1343.2)
  Bottom w6: P200.4@363.85,1200.27 v1(363.85,1255)
RADIO_PD10: P201.7 U1.8 | length 1587.5
  Top w6: v1@708.66,1369.06 U1.8@708.66,1413.39
  Inner Layer 2 w6: v1@464.85,205 v1(464.85,197) 479.98,197 501.98,175 567.72,175 579.85,187.13 579.85,281.13 631.28,332.56 631.28,835.76 604.85,862.19 604.85,925.9 576.29,954.46 576.29,954.69 554.85,976.13 554.85,1015.09 543.35,1026.59 543.35,1264.63 579.1,1300.39 586.51,1300.39 601.12,1315 646.98,1315 702.98,1371 704.78,1369.2 v1(711.07,1369.2)
  Bottom w6: P201.7@462.4,139.76 462.4,194.55 v1(464.85,197)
